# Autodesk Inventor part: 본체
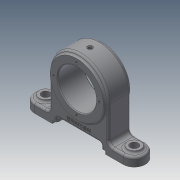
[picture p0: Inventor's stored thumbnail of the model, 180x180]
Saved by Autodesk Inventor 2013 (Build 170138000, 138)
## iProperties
Created: 2019-05
Part Number: 본체
Material: Generic
Document SubType Name: Modeling
Designer: user
Density: 1 g/cm^3
Mass: 168.894 g
Surface Area: 318.8 cm^2
Volume: 168.894 cm^3
Author: user
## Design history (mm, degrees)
sketch "스케치1"
  geometry: C1 r 40 at (0, 0); 1 further point
  constraints: 1 centre point, 1 coincident
  dimensions: "d0" = 80 diameter of C1
extrude "돌출1" new body sketch "스케치1" stored distance "d2" = 30; taper "d3" = 0 deg
sketch "스케치2"
  geometry: C1 r 40 at (0, 0) reference; C2 r 36 at (0, 0)
  constraints: 1 centre point, 1 coincident
  dimensions: "d4" = 72 diameter of C2
extrude "돌출2" join sketch "스케치2" distance "d6" = 3; taper "d7" = 0 deg
sketch "스케치3"
  geometry: C1 r 36 at (0, 0) reference; C2 r 26 at (0, 0)
  constraints: 1 centre point, 1 coincident
  dimensions: "d8" = 52 diameter of C2
extrude "돌출3" cut sketch "스케치3" stored distance "d9" = 3; taper "d10" = 0 deg
sketch "스케치4"
  geometry: L1 (0, 0)-(0, 31); C1 r 36 at (0, 0) reference; 1 further point
  constraints: 2 end point, 1 coincident, 1 vertical
  dimensions: "d11" = 31 distance of L1.start L1.end
hole "구멍1" sketch "스케치4" at (0, 31) diameter "d12" = 3.242; stored, may be unused: countersink angle "d16" = 90 deg, drill point angle "d18" = 118 deg; dims "d13" = 6, "d14" = 7, "d15" = 1, "d17" = 8
node "작업 평면1"
sketch "스케치5"
  geometry: L1 (-75, -15)-(75, -15); L2 (75, -15)-(75, 15); L3 (75, 15)-(-75, 15); L4 (-75, 15)-(-75, -15); L5 (-75, -15)-(75, 15); L6 (75, -15)-(-75, 15); 1 further point
  constraints: 12 end point, 2 midpoint, 2 parallel, 1 horizontal, 1 perpendicular
  dimensions: "d23" = 150 distance of L3.end L2.end; "d24" = 30 distance of L2.end L1.end
extrude "돌출4" join sketch "스케치5" distance "d25" = 12; taper "d26" = 0 deg
sketch "스케치6"
  geometry: L1 (-75, -60)-(-75, -48) reference; L2 (-75, -48)-(75, -48) reference; L3 (75, -48)-(75, -60) reference; L4 (75, -60)-(-75, -60) reference; L5 (-40, 0)-(-40, -48); L6 (40, 0)-(40, -48); C1 r 26 at (0, 0) reference; A1 r 40 centre (0, 0) between (-40, 0) and (40, 0) reference; 1 further point
  constraints: 4 end point, 2 perpendicular, 2 point on circle, 2 point on line, 2 tangent
extrude "돌출5" join sketch "스케치6" stored distance "d27" = 30; taper "d28" = 0 deg
sketch "스케치7"
  geometry: L1 (-75, -60)-(75, -60) reference; L2 (-36, -60)-(36, -60); L3 (36, -60)-(36, -56); L4 (36, -56)-(-36, -56); L5 (-36, -56)-(-36, -60); C1 r 36 at (0, 0) reference; 1 further point
  constraints: 8 end point, 2 parallel, 1 horizontal, 1 midpoint, 1 perpendicular, 1 point on line, 1 vertical alignment
  dimensions: "d29" = 72 distance of L4.end L3.end; "d30" = 4 distance of L3.end L2.end
extrude "돌출6" cut sketch "스케치7" stored distance "d31" = 30; taper "d32" = 0 deg
sketch "스케치8"
  geometry: L1 (-36, -56)-(36, -56) reference; L2 (-30, -56)-(30, -56); L3 (30, -56)-(30, -50); L4 (30, -50)-(-30, -50); L5 (-30, -50)-(-30, -56); A1 r 40 centre (0, 0) between (40, 0) and (-40, 0) reference; 1 further point
  constraints: 8 end point, 2 parallel, 1 horizontal, 1 midpoint, 1 perpendicular, 1 point on line, 1 vertical alignment
  dimensions: "d33" = 60 distance of L4.end L3.end; "d34" = 6 distance of L3.end L2.end
extrude "돌출7" cut sketch "스케치8" stored distance "d35" = 30; taper "d36" = 0 deg
fillet "모깎기1" dims "d37" = 6
fillet "모깎기2" dims "d38" = 3
fillet "모깎기3" dims "d39" = 3
fillet "모깎기4" dims "d40" = 3
fillet "모깎기5" dims "d41" = 3
sketch "스케치9"
  geometry: C1 r 1.5 at (0, 26); 1 further point
  constraints: 2 vertical alignment, 1 centre point, 1 other
  dimensions: "d42" = 3 diameter of C1
extrude "돌출8" cut sketch "스케치9" stored distance "d43" = 30; taper "d44" = 0 deg
node "작업 평면2"
sketch "스케치10"
  geometry: C1 r 1 at (0, 0); 1 further point
  constraints: 1 centre point, 1 coincident
  dimensions: "d46" = 2 diameter of C1
extrude "돌출9" cut sketch "스케치10" stored distance "d47" = 30; taper "d48" = 0 deg
sketch "스케치11"
  geometry: 2 further points
  constraints: 1 coincident
hole "구멍2" sketch "스케치11" at (0, 0) diameter "d49" = 4.917; stored, may be unused: countersink angle "d53" = 90 deg, drill point angle "d55" = 118 deg; dims "d50" = 8, "d51" = 7, "d52" = 1, "d54" = 10
fillet "모깎기6" dims "d56" = 15
sketch "스케치12"
  geometry: L1 (-30.317, -15)-(-46, -15) reference; L2 (-46, -15)-(-60, -15) reference; L3 (-60, 15)-(-46, 15) reference; L4 (-46, 15)-(-46, -15) reference; L5 (27, -14.828)-(-27, -14.828) reference; L6 (46, -15)-(30.317, -15) reference; L7 (46, -15)-(46, 15) reference; L8 (30.317, 15)-(46, 15) reference; L9 (-27, 14.828)-(27, 14.828) reference; L10 (-46, 15)-(-30.317, 15) reference; L11 (60, -15)-(46, -15) reference; L12 (46, 15)-(60, 15) reference; C1 r 9 at (60, 0); C2 r 9 at (-60, 0); A1 r 15 centre (-60, 0) between (-60, 15) and (-60, -15) reference; A2 r 15 centre (60, 0) between (60, -15) and (60, 15) reference; 1 further point
  constraints: 2 centre point, 2 coincident, 4 other
  dimensions: "d57" = 18 diameter of C1; "d58" = 18 diameter of C2
extrude "돌출10" join sketch "스케치12" distance "d59" = 3; taper "d60" = 0 deg
sketch "스케치13"
  geometry: C1 r 9 at (0, 0) reference; C2 r 9 at (120, 0) reference; 3 further points
  constraints: 2 coincident
hole "구멍3" sketch "스케치13" at (0, 0), (120, 0) diameter "d61" = 11; stored, may be unused: countersink angle "d65" = 90 deg, drill point angle "d67" = 118 deg; dims "d62" = 8, "d63" = 7, "d64" = 1, "d66" = 10
fillet "모깎기7" dims "d68" = 3
fillet "모깎기8" dims "d69" = 3
chamfer "모따기1" distance "d70" = 1; stored, may be unused: second distance "d71" = 2, angle "d72" = 45 deg
sketch "스케치14"
  geometry: L1 (-27, -50)-(27, -50) reference; A1 r 39 centre (0, 0) between (-37, -12.329) and (37, -12.329) reference; 1 further point
  constraints: 1 vertical alignment, 1 other
  dimensions: "d73" = 7 distance from line of point (0, -43) L1
feature "엠보싱1" sketch "스케치14" dims "d74" = 0.5, "d75" = 0
node "솔리드1"
mirror "대칭1"
pattern_circular "원형 패턴1" dims angle "d20" = 360 deg
mirror "대칭2"
node "투영된 루프1"
node "절단 모서리 투영1"
node "절단 모서리 투영2"
